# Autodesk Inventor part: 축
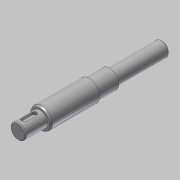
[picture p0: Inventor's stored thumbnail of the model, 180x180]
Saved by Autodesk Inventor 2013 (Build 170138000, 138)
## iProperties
Created: 2019-01
Part Number: 축
Material: 강철, 탄소
Document SubType Name: Modeling
Designer: mduedu
Density: 7.87 g/cm^3
Mass: 452.778 g
Surface Area: 120.904 cm^2
Volume: 57.5322 cm^3
Author: mduedu
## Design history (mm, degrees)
sketch "스케치1"
  geometry: L1 (0, 0)-(26, 0); L2 (26, 0)-(26, 9); L3 (26, 9)-(0, 9); L4 (0, 9)-(0, 0); L5 (26, 0)-(84, 0); L6 (84, 0)-(84, 12.5); L7 (84, 12.5)-(26, 12.5); L8 (26, 12.5)-(26, 0); L9 (84, 0)-(108, 0); L10 (108, 0)-(108, 11); L11 (108, 11)-(84, 11); L12 (84, 11)-(84, 0); L13 (108, 0)-(170, 0); L14 (170, 0)-(170, 8.5); L15 (170, 8.5)-(108, 8.5); L16 (108, 8.5)-(108, 0)
  constraints: 32 end point, 8 parallel, 4 horizontal, 4 perpendicular
  dimensions: "d0" = 170 distance between parallel lines of L14 L4; "d2" = 26 distance of L2.end L3.end; "d3" = 24 distance of L10.end L11.end; "d4" = 62 distance of L14.end L15.end; "d5" = 18 diameter of L3 L1; "d6" = 25 diameter of L7 L5; "d7" = 22 diameter of L11 L9; "d8" = 17 diameter of L15 L13
revolve "회전1" sketch "스케치1" stored, may be unused: angle "d9" = 90 deg
node "작업 평면1"
sketch "스케치2" dims "d13" = 18
  geometry: L1 (6, -3)-(-6, -3); L2 (-6, -3)-(-6, 3); L3 (-6, 3)-(6, 3); L4 (6, 3)-(6, -3); L5 (13, 9)-(13, -9) reference; 3 further points
  constraints: 8 end point, 2 midpoint, 2 parallel, 2 vertical alignment, 1 horizontal, 1 horizontal alignment, 1 perpendicular, 4 other
  dimensions: "d10" = 6 distance between parallel lines of L3 L1; "d12" = 4 dimension on L5
extrude "돌출1" cut sketch "스케치2" distance "d14" = 3.5; taper "d15" = 0 deg
node "작업 평면2"
sketch "스케치3" dims "d19" = 20
  geometry: L1 (-21.5, -2.5)-(-6.5, -2.5); L2 (-6.5, -2.5)-(-6.5, 2.5); L3 (-6.5, 2.5)-(-21.5, 2.5); L4 (-21.5, 2.5)-(-21.5, -2.5); L5 (-31, 8.5)-(-31, -8.5) reference; 3 further points
  constraints: 8 end point, 2 midpoint, 2 parallel, 2 vertical alignment, 1 horizontal, 1 horizontal alignment, 1 perpendicular, 4 other
  dimensions: "d16" = 5 distance between parallel lines of L3 L1; "d18" = 7 dimension on L5
extrude "돌출2" cut sketch "스케치3" distance "d20" = 3; taper "d21" = 0 deg
chamfer "모따기1" distance "d22" = 1; stored, may be unused: second distance "d23" = 2, angle "d24" = 45 deg
chamfer "모따기2" distance "d25" = 2; stored, may be unused: second distance "d26" = 2, angle "d27" = 30 deg
fillet "모깎기2" dims "d30" = 2
node "솔리드1"
